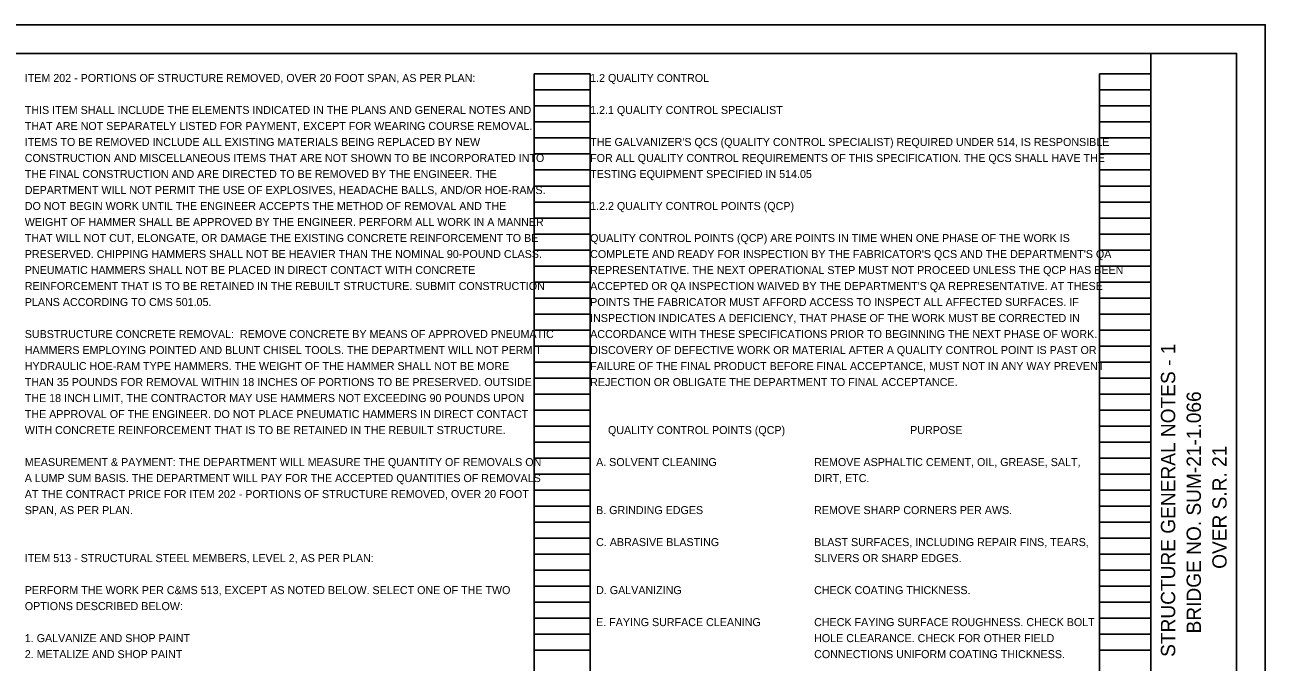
# Model space of a CAD drawing. Extents: x 0 to 34, y 0 to 22.
# Drawn here: x 12.29 to 34, y 10.85 to 22 of the extents above; entities that cross this region are included whole.
import ezdxf

# ---------------------------------------------------------------- set-up
doc = ezdxf.new("R2010")
doc.units = 0
for name, color, linetype in [('SH_Border', 7, 'Continuous'), ('SH_Cut_Line', 7, 'Continuous'), ('SH_Data', 7, 'Continuous'), ('SH_Text', 7, 'Continuous')]:
    doc.layers.add(name, color=color, linetype=linetype)

msp = doc.modelspace()

# ---------------------------------------------------------------- linework, layer by layer
at = {"layer": 'SH_Border'}
msp.add_line((32, 0.5), (32, 21.5), dxfattribs=at)
msp.add_lwpolyline([(1.5, 21.5), (33.5, 21.5), (33.5, 0.5), (1.5, 0.5)], close=True, dxfattribs=at)
at = {"layer": 'SH_Cut_Line'}
msp.add_lwpolyline([(0, 0), (34, 0), (34, 22), (0, 22)], close=True, dxfattribs=at)
at = {"layer": 'SH_Data'}
for p, q in [((21.207, 0.98), (21.207, 21.14)), ((21.207, 21.14), (22.187, 21.14)), ((22.187, 0.98), (22.187, 21.14)), ((31.1, 0.98), (31.1, 21.14)), ((31.1, 21.14), (32, 21.14)), ((32, 0.98), (32, 21.14)), ((21.207, 20.86), (22.187, 20.86)), ((31.1, 20.86), (32, 20.86)), ((21.207, 20.58), (22.187, 20.58)), ((31.1, 20.58), (32, 20.58)), ((21.207, 20.3), (22.187, 20.3)), ((31.1, 20.3), (32, 20.3)), ((21.207, 20.02), (22.187, 20.02)), ((31.1, 20.02), (32, 20.02)), ((21.207, 19.74), (22.187, 19.74)), ((31.1, 19.74), (32, 19.74)), ((21.207, 19.46), (22.187, 19.46)), ((31.1, 19.46), (32, 19.46)), ((21.207, 19.18), (22.187, 19.18)), ((31.1, 19.18), (32, 19.18)), ((21.207, 18.9), (22.187, 18.9)), ((31.1, 18.9), (32, 18.9)), ((21.207, 18.62), (22.187, 18.62)), ((31.1, 18.62), (32, 18.62)), ((21.207, 18.34), (22.187, 18.34)), ((31.1, 18.34), (32, 18.34)), ((21.207, 18.06), (22.187, 18.06)), ((31.1, 18.06), (32, 18.06)), ((21.207, 17.78), (22.187, 17.78)), ((31.1, 17.78), (32, 17.78)), ((21.207, 17.5), (22.187, 17.5)), ((31.1, 17.5), (32, 17.5)), ((21.207, 17.22), (22.187, 17.22)), ((31.1, 17.22), (32, 17.22)), ((21.207, 16.94), (22.187, 16.94)), ((31.1, 16.94), (32, 16.94)), ((21.207, 16.66), (22.187, 16.66)), ((31.1, 16.66), (32, 16.66)), ((21.207, 16.38), (22.187, 16.38)), ((31.1, 16.38), (32, 16.38)), ((21.207, 16.1), (22.187, 16.1)), ((31.1, 16.1), (32, 16.1)), ((21.207, 15.82), (22.187, 15.82)), ((31.1, 15.82), (32, 15.82)), ((21.207, 15.54), (22.187, 15.54)), ((31.1, 15.54), (32, 15.54)), ((21.207, 15.26), (22.187, 15.26)), ((31.1, 15.26), (32, 15.26)), ((21.207, 14.98), (22.187, 14.98)), ((31.1, 14.98), (32, 14.98)), ((21.207, 14.7), (22.187, 14.7)), ((31.1, 14.7), (32, 14.7)), ((21.207, 14.42), (22.187, 14.42)), ((31.1, 14.42), (32, 14.42)), ((21.207, 14.14), (22.187, 14.14)), ((31.1, 14.14), (32, 14.14)), ((21.207, 13.86), (22.187, 13.86)), ((31.1, 13.86), (32, 13.86)), ((21.207, 13.58), (22.187, 13.58)), ((31.1, 13.58), (32, 13.58)), ((21.207, 13.3), (22.187, 13.3)), ((31.1, 13.3), (32, 13.3)), ((21.207, 13.02), (22.187, 13.02)), ((31.1, 13.02), (32, 13.02)), ((21.207, 12.74), (22.187, 12.74)), ((31.1, 12.74), (32, 12.74)), ((21.207, 12.46), (22.187, 12.46)), ((31.1, 12.46), (32, 12.46)), ((21.207, 12.18), (22.187, 12.18)), ((31.1, 12.18), (32, 12.18)), ((21.207, 11.9), (22.187, 11.9)), ((31.1, 11.9), (32, 11.9)), ((21.207, 11.62), (22.187, 11.62)), ((31.1, 11.62), (32, 11.62)), ((21.207, 11.34), (22.187, 11.34)), ((31.1, 11.34), (32, 11.34)), ((21.207, 11.06), (22.187, 11.06)), ((31.1, 11.06), (32, 11.06))]:
    msp.add_line(p, q, dxfattribs=at)

# ---------------------------------------------------------------- texts
for s, p in [('STRUCTURE GENERAL NOTES - 1', (32.425, 10.942)), ('BRIDGE NO. SUM-21-1.066', (32.875, 11.352)), ('OVER S.R. 21', (33.325, 12.482))]:
    msp.add_text(s, height=0.25, rotation=90, dxfattribs=at).set_placement(p)
at = {"layer": 'SH_Text'}
for s, p in [('ITEM 202 - PORTIONS OF STRUCTURE REMOVED, OVER 20 FOOT SPAN, AS PER PLAN:', (12.293, 21)), ('1.2 QUALITY CONTROL', (22.187, 21)), ('THIS ITEM SHALL INCLUDE THE ELEMENTS INDICATED IN THE PLANS AND GENERAL NOTES AND ', (12.293, 20.44)), ('1.2.1 QUALITY CONTROL SPECIALIST', (22.187, 20.44)), ('THAT ARE NOT SEPARATELY LISTED FOR PAYMENT, EXCEPT FOR WEARING COURSE REMOVAL. ', (12.293, 20.16)), ('ITEMS TO BE REMOVED INCLUDE ALL EXISTING MATERIALS BEING REPLACED BY NEW ', (12.293, 19.88)), ("THE GALVANIZER'S QCS (QUALITY CONTROL SPECIALIST) REQUIRED UNDER 514, IS RESPONSIBLE ", (22.187, 19.88)), ('CONSTRUCTION AND MISCELLANEOUS ITEMS THAT ARE NOT SHOWN TO BE INCORPORATED INTO ', (12.293, 19.6)), ('FOR ALL QUALITY CONTROL REQUIREMENTS OF THIS SPECIFICATION. THE QCS SHALL HAVE THE ', (22.187, 19.6)), ('THE FINAL CONSTRUCTION AND ARE DIRECTED TO BE REMOVED BY THE ENGINEER. THE ', (12.293, 19.32)), ('TESTING EQUIPMENT SPECIFIED IN 514.05', (22.187, 19.32)), ('DEPARTMENT WILL NOT PERMIT THE USE OF EXPLOSIVES, HEADACHE BALLS, AND/OR HOE-RAMS. ', (12.293, 19.04)), ('DO NOT BEGIN WORK UNTIL THE ENGINEER ACCEPTS THE METHOD OF REMOVAL AND THE ', (12.293, 18.76)), ('1.2.2 QUALITY CONTROL POINTS (QCP)', (22.187, 18.76)), ('WEIGHT OF HAMMER SHALL BE APPROVED BY THE ENGINEER. PERFORM ALL WORK IN A MANNER ', (12.293, 18.48)), ('THAT WILL NOT CUT, ELONGATE, OR DAMAGE THE EXISTING CONCRETE REINFORCEMENT TO BE ', (12.293, 18.2)), ('QUALITY CONTROL POINTS (QCP) ARE POINTS IN TIME WHEN ONE PHASE OF THE WORK IS ', (22.187, 18.2)), ('PRESERVED. CHIPPING HAMMERS SHALL NOT BE HEAVIER THAN THE NOMINAL 90-POUND CLASS. ', (12.293, 17.92)), ("COMPLETE AND READY FOR INSPECTION BY THE FABRICATOR'S QCS AND THE DEPARTMENT'S QA ", (22.187, 17.92)), ('PNEUMATIC HAMMERS SHALL NOT BE PLACED IN DIRECT CONTACT WITH CONCRETE ', (12.293, 17.64)), ('REPRESENTATIVE. THE NEXT OPERATIONAL STEP MUST NOT PROCEED UNLESS THE QCP HAS BEEN ', (22.187, 17.64)), ('REINFORCEMENT THAT IS TO BE RETAINED IN THE REBUILT STRUCTURE. SUBMIT CONSTRUCTION ', (12.293, 17.36)), ("ACCEPTED OR QA INSPECTION WAIVED BY THE DEPARTMENT'S QA REPRESENTATIVE. AT THESE ", (22.187, 17.36)), ('PLANS ACCORDING TO CMS 501.05.', (12.293, 17.08)), ('POINTS THE FABRICATOR MUST AFFORD ACCESS TO INSPECT ALL AFFECTED SURFACES. IF ', (22.187, 17.08)), ('INSPECTION INDICATES A DEFICIENCY, THAT PHASE OF THE WORK MUST BE CORRECTED IN ', (22.187, 16.8)), ('SUBSTRUCTURE CONCRETE REMOVAL:  REMOVE CONCRETE BY MEANS OF APPROVED PNEUMATIC ', (12.293, 16.52)), ('ACCORDANCE WITH THESE SPECIFICATIONS PRIOR TO BEGINNING THE NEXT PHASE OF WORK. ', (22.187, 16.52)), ('HAMMERS EMPLOYING POINTED AND BLUNT CHISEL TOOLS. THE DEPARTMENT WILL NOT PERMIT ', (12.293, 16.24)), ('DISCOVERY OF DEFECTIVE WORK OR MATERIAL AFTER A QUALITY CONTROL POINT IS PAST OR ', (22.187, 16.24)), ('HYDRAULIC HOE-RAM TYPE HAMMERS. THE WEIGHT OF THE HAMMER SHALL NOT BE MORE ', (12.293, 15.96)), ('FAILURE OF THE FINAL PRODUCT BEFORE FINAL ACCEPTANCE, MUST NOT IN ANY WAY PREVENT ', (22.187, 15.96)), ('THAN 35 POUNDS FOR REMOVAL WITHIN 18 INCHES OF PORTIONS TO BE PRESERVED. OUTSIDE ', (12.293, 15.68)), ('REJECTION OR OBLIGATE THE DEPARTMENT TO FINAL ACCEPTANCE.', (22.187, 15.68)), ('THE 18 INCH LIMIT, THE CONTRACTOR MAY USE HAMMERS NOT EXCEEDING 90 POUNDS UPON ', (12.293, 15.4)), ('THE APPROVAL OF THE ENGINEER. DO NOT PLACE PNEUMATIC HAMMERS IN DIRECT CONTACT ', (12.293, 15.12)), ('WITH CONCRETE REINFORCEMENT THAT IS TO BE RETAINED IN THE REBUILT STRUCTURE.', (12.293, 14.84)), ('      QUALITY CONTROL POINTS (QCP)', (22.187, 14.84)), ('PURPOSE', (27.787, 14.84)), ('MEASUREMENT & PAYMENT: THE DEPARTMENT WILL MEASURE THE QUANTITY OF REMOVALS ON ', (12.293, 14.28)), ('  A. SOLVENT CLEANING', (22.187, 14.28)), ('REMOVE ASPHALTIC CEMENT, OIL, GREASE, SALT, ', (26.107, 14.28)), ('A LUMP SUM BASIS. THE DEPARTMENT WILL PAY FOR THE ACCEPTED QUANTITIES OF REMOVALS ', (12.293, 14)), ('DIRT, ETC.', (26.107, 14)), ('AT THE CONTRACT PRICE FOR ITEM 202 - PORTIONS OF STRUCTURE REMOVED, OVER 20 FOOT ', (12.293, 13.72)), ('SPAN, AS PER PLAN.', (12.293, 13.44)), ('  B. GRINDING EDGES', (22.187, 13.44)), ('REMOVE SHARP CORNERS PER AWS.', (26.107, 13.44)), ('  C. ABRASIVE BLASTING', (22.187, 12.88)), ('BLAST SURFACES, INCLUDING REPAIR FINS, TEARS, ', (26.107, 12.88)), ('ITEM 513 - STRUCTURAL STEEL MEMBERS, LEVEL 2, AS PER PLAN:', (12.293, 12.6)), ('SLIVERS OR SHARP EDGES.', (26.107, 12.6)), ('PERFORM THE WORK PER C&MS 513, EXCEPT AS NOTED BELOW. SELECT ONE OF THE TWO ', (12.293, 12.04)), ('  D. GALVANIZING', (22.187, 12.04)), ('CHECK COATING THICKNESS.', (26.107, 12.04)), ('OPTIONS DESCRIBED BELOW:', (12.293, 11.76)), ('  E. FAYING SURFACE CLEANING', (22.187, 11.48)), ('CHECK FAYING SURFACE ROUGHNESS. CHECK BOLT ', (26.107, 11.48)), ('1. GALVANIZE AND SHOP PAINT ', (12.293, 11.2)), ('HOLE CLEARANCE. CHECK FOR OTHER FIELD ', (26.107, 11.2)), ('2. METALIZE AND SHOP PAINT', (12.293, 10.92)), ('CONNECTIONS UNIFORM COATING THICKNESS.', (26.107, 10.92))]:
    msp.add_text(s, height=0.14, dxfattribs=at).set_placement(p)

doc.saveas('drawing.dxf')
